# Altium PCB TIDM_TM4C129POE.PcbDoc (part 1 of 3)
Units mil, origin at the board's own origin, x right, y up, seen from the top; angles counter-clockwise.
Board outline 4950 x 3450 mil, 4 copper layers (Component Side, Ground Plane, Power Plane, Solder Side), stack 59.6 mil thick; 159 components, 154 nets, 570 pads, 297 vias.
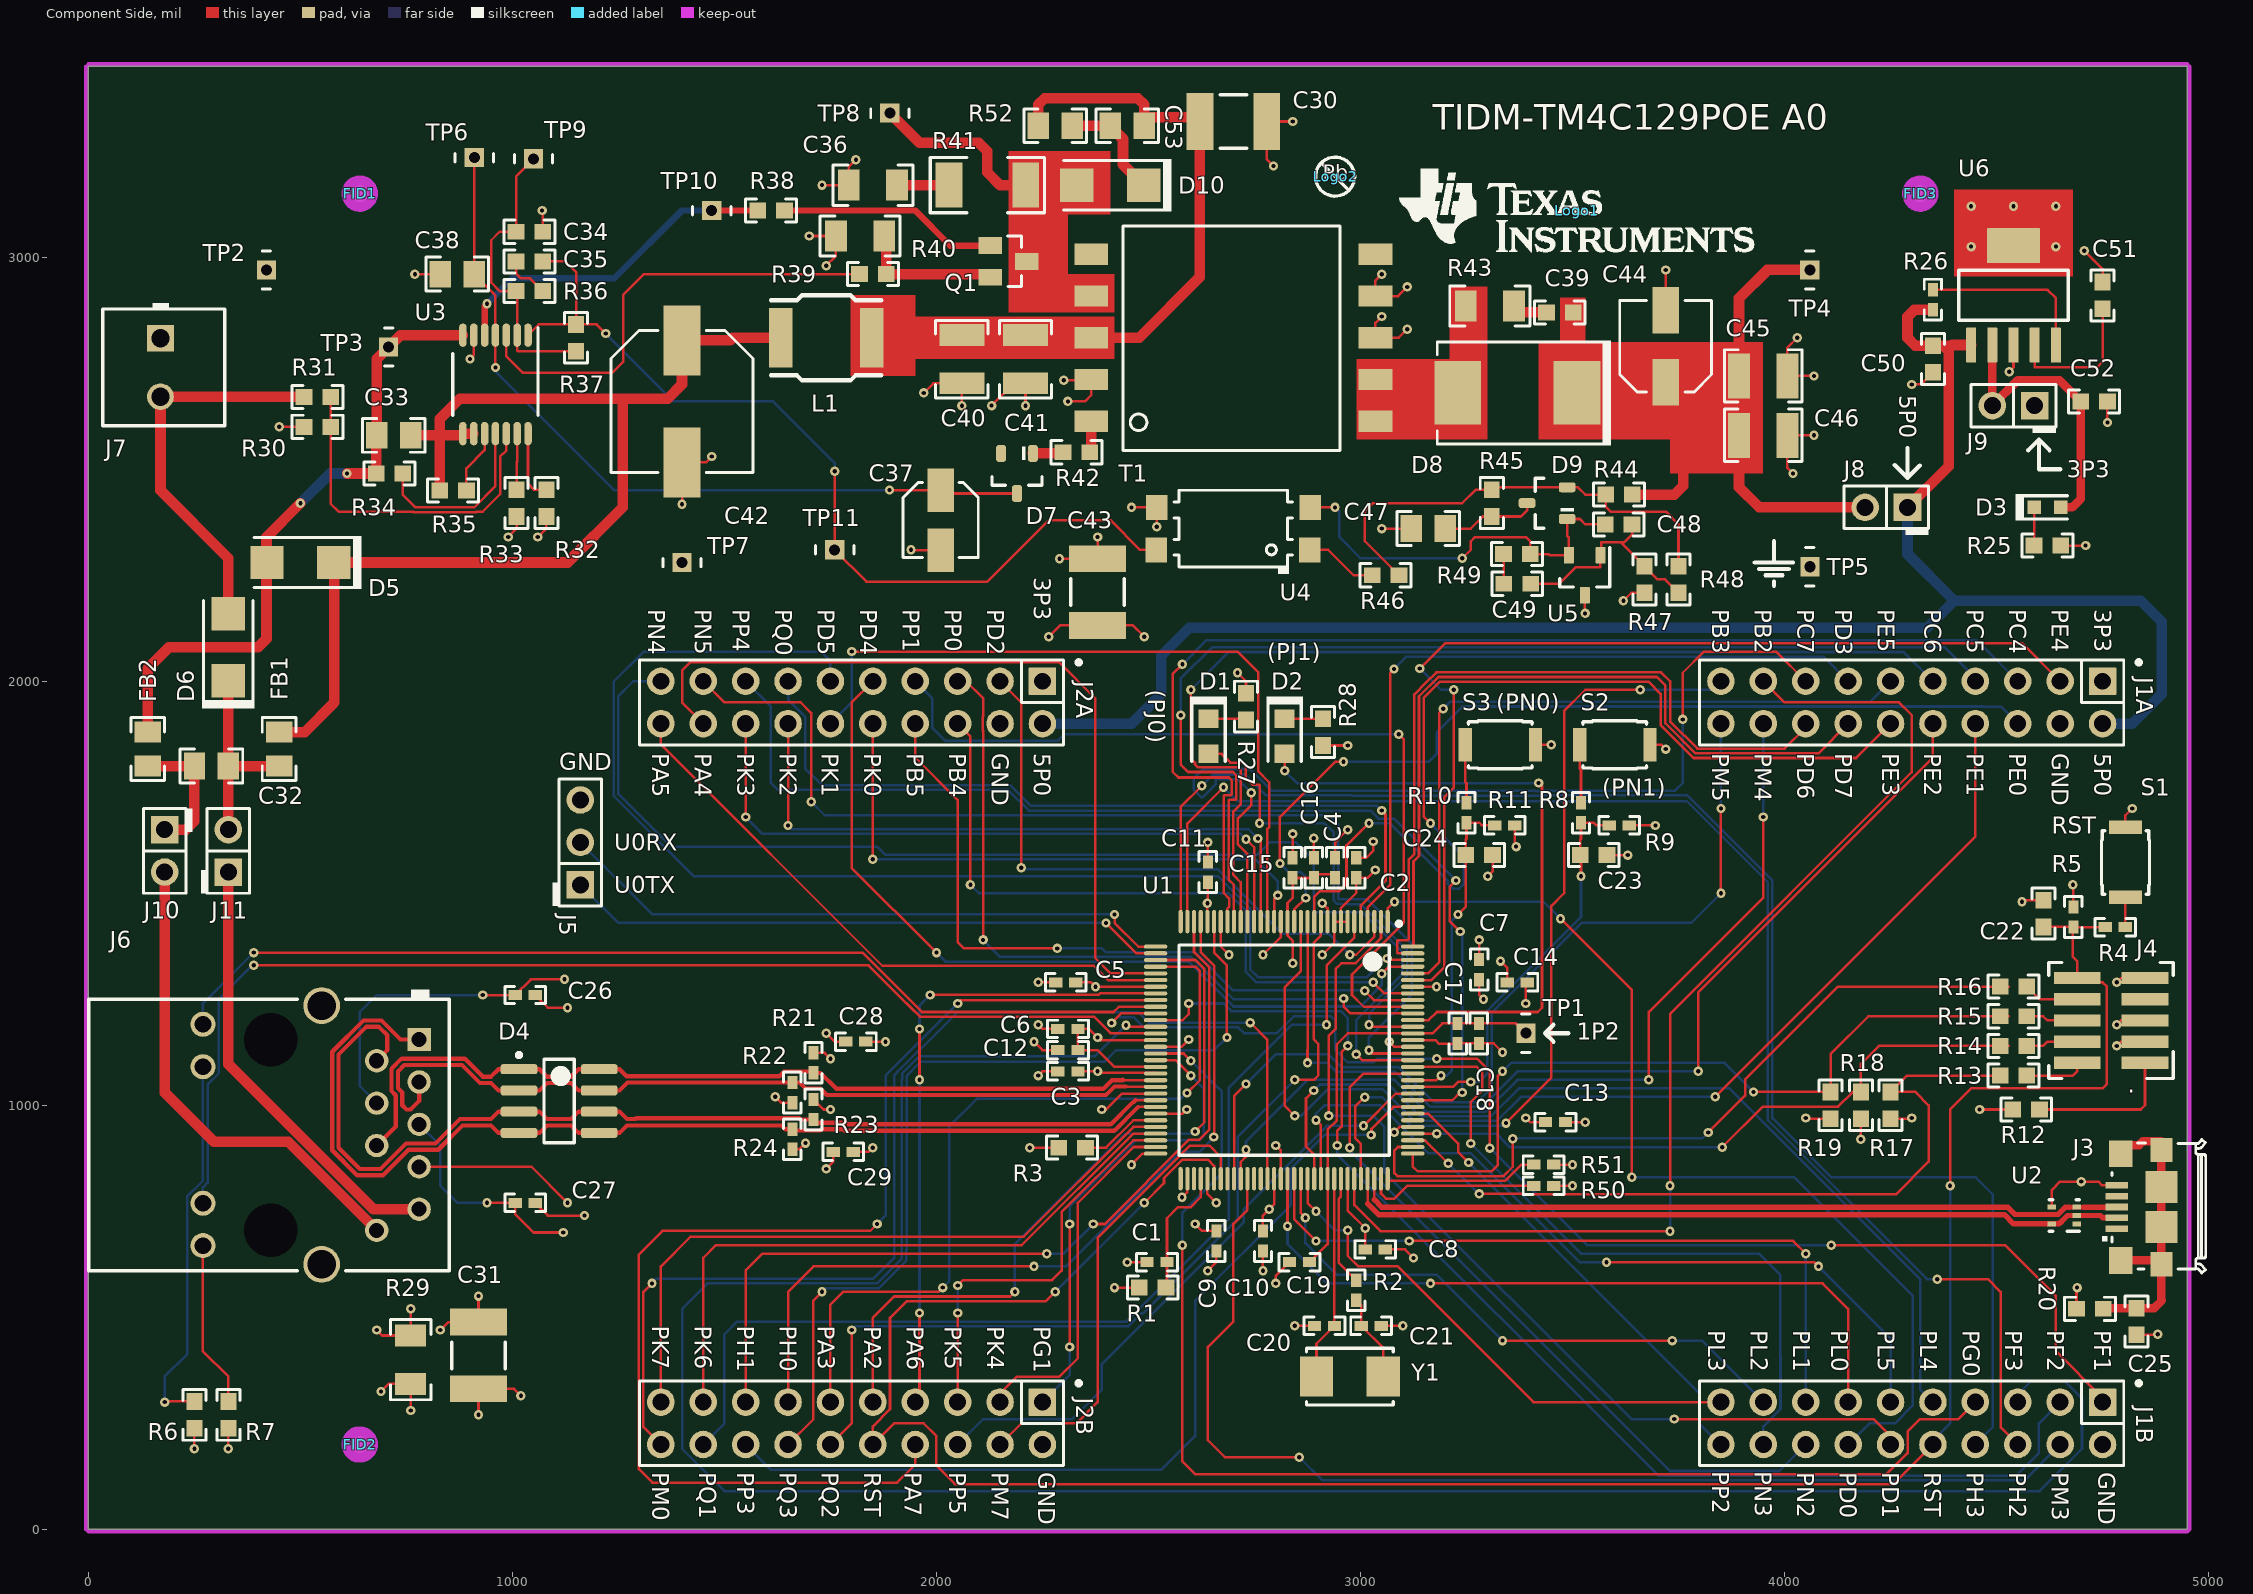
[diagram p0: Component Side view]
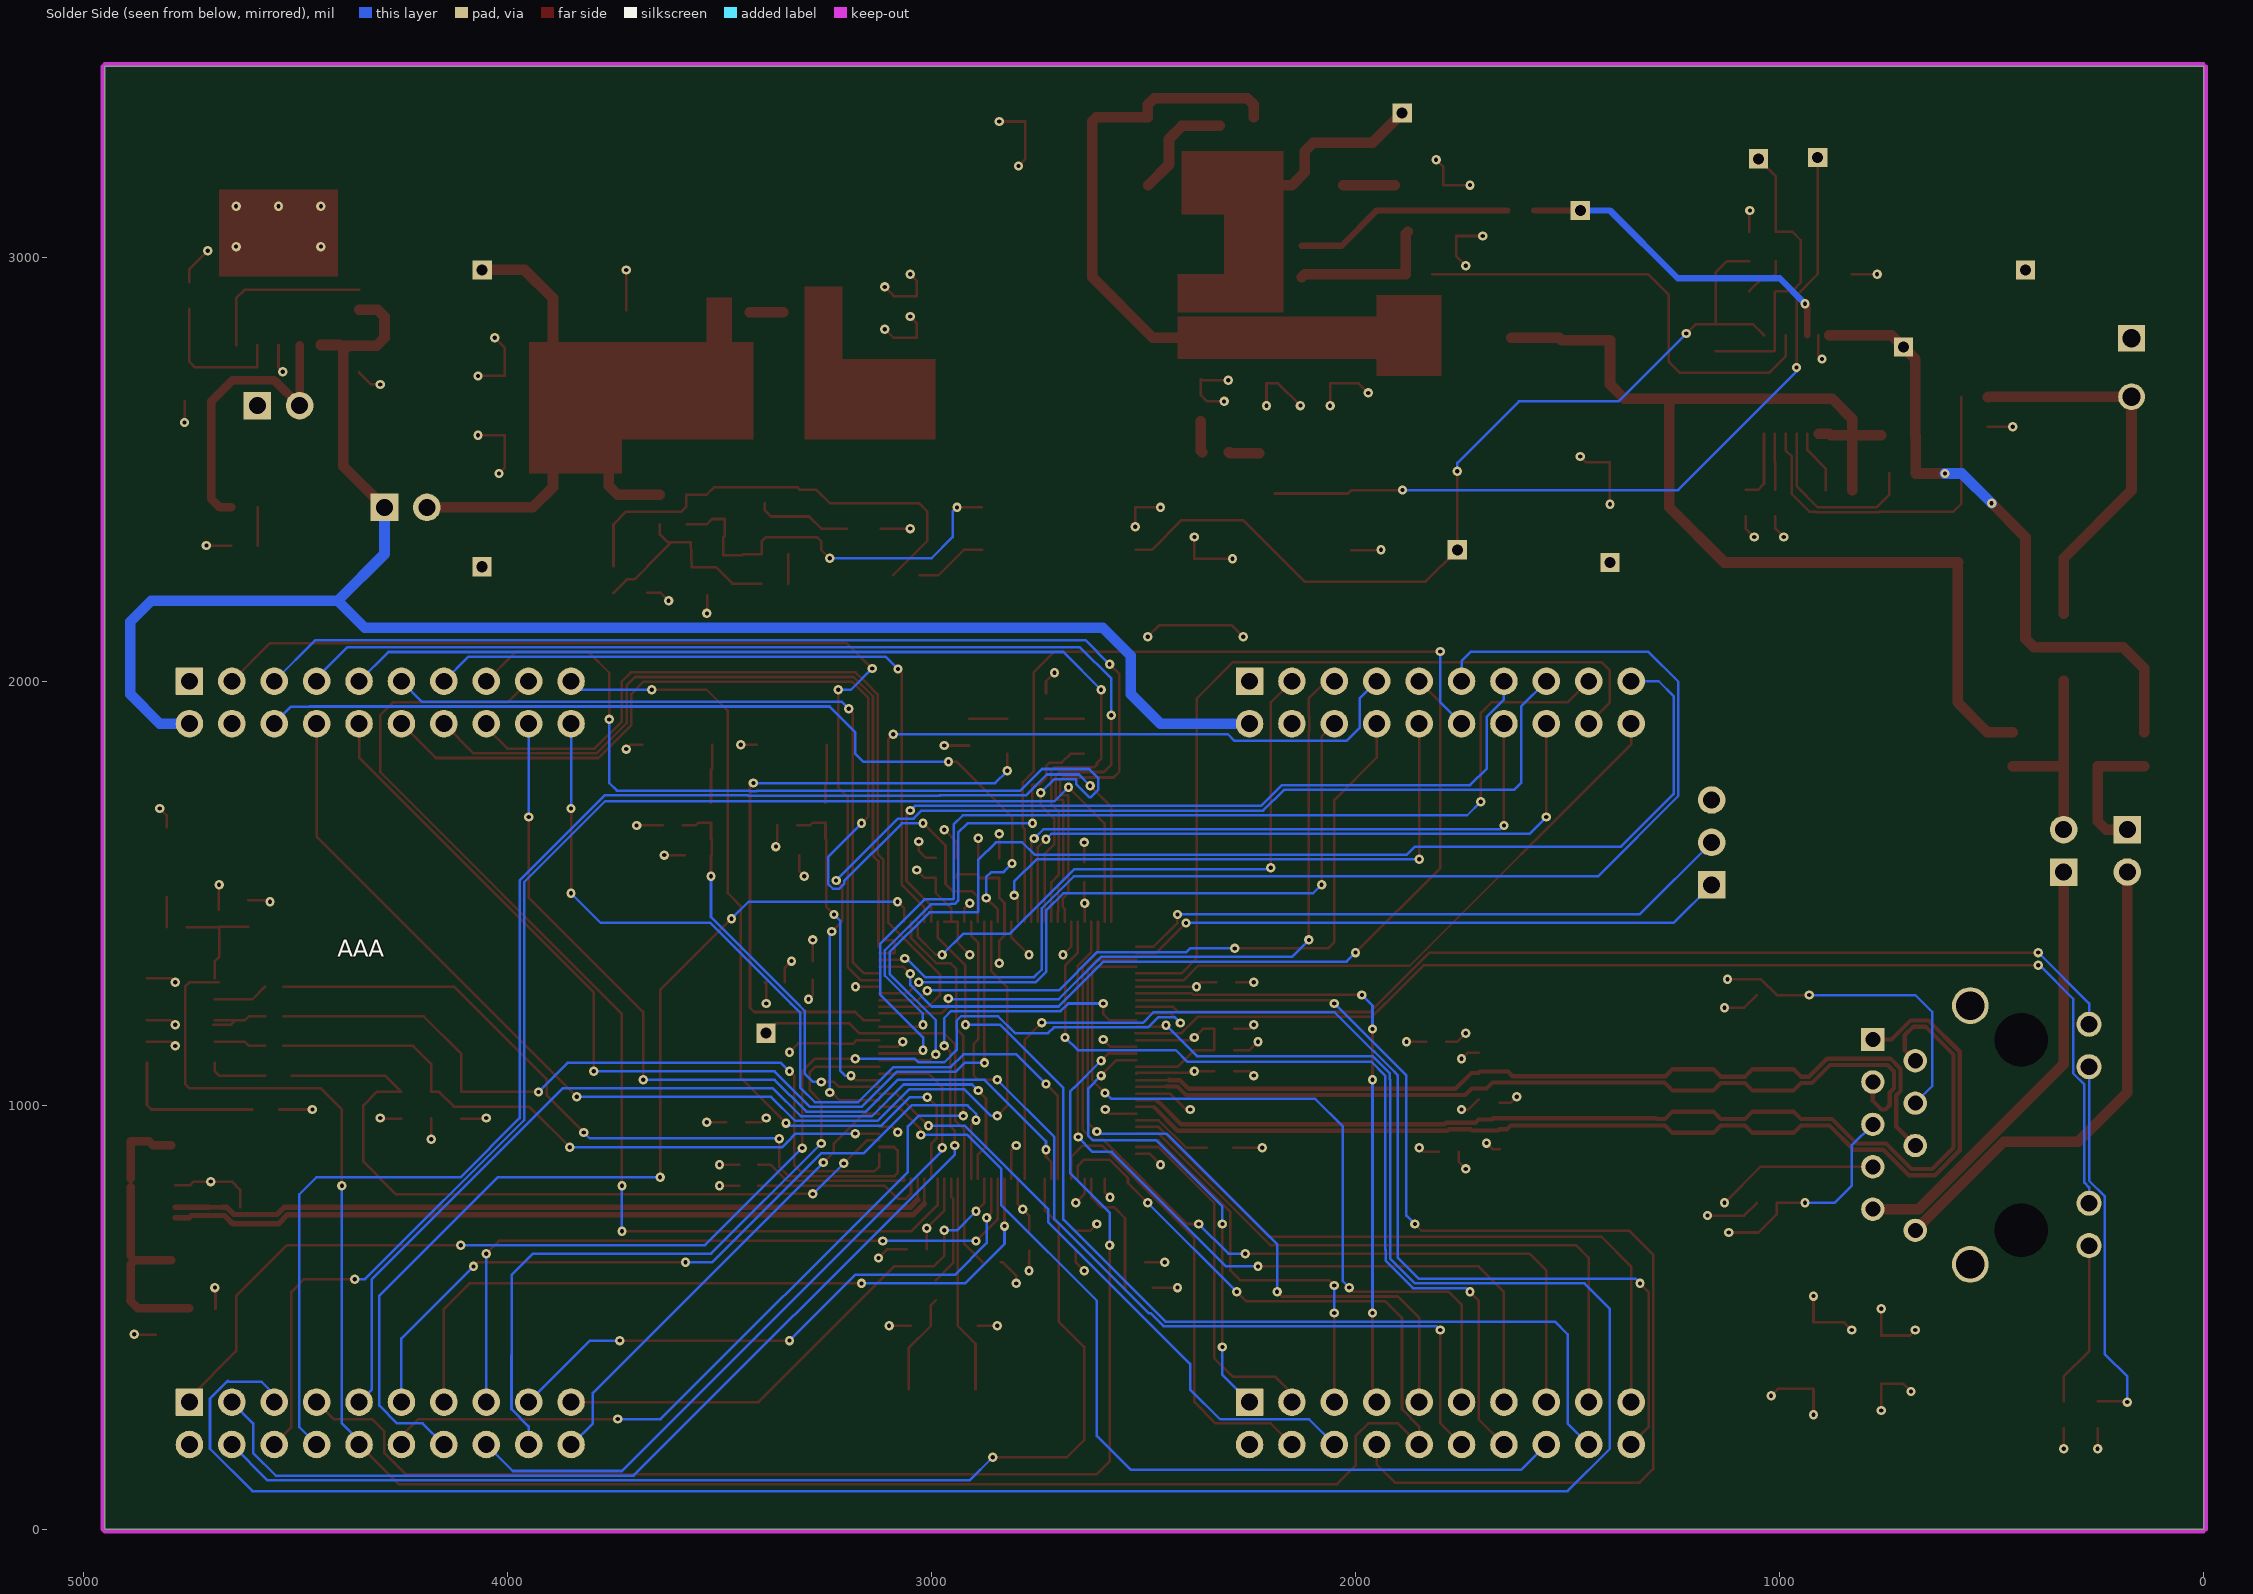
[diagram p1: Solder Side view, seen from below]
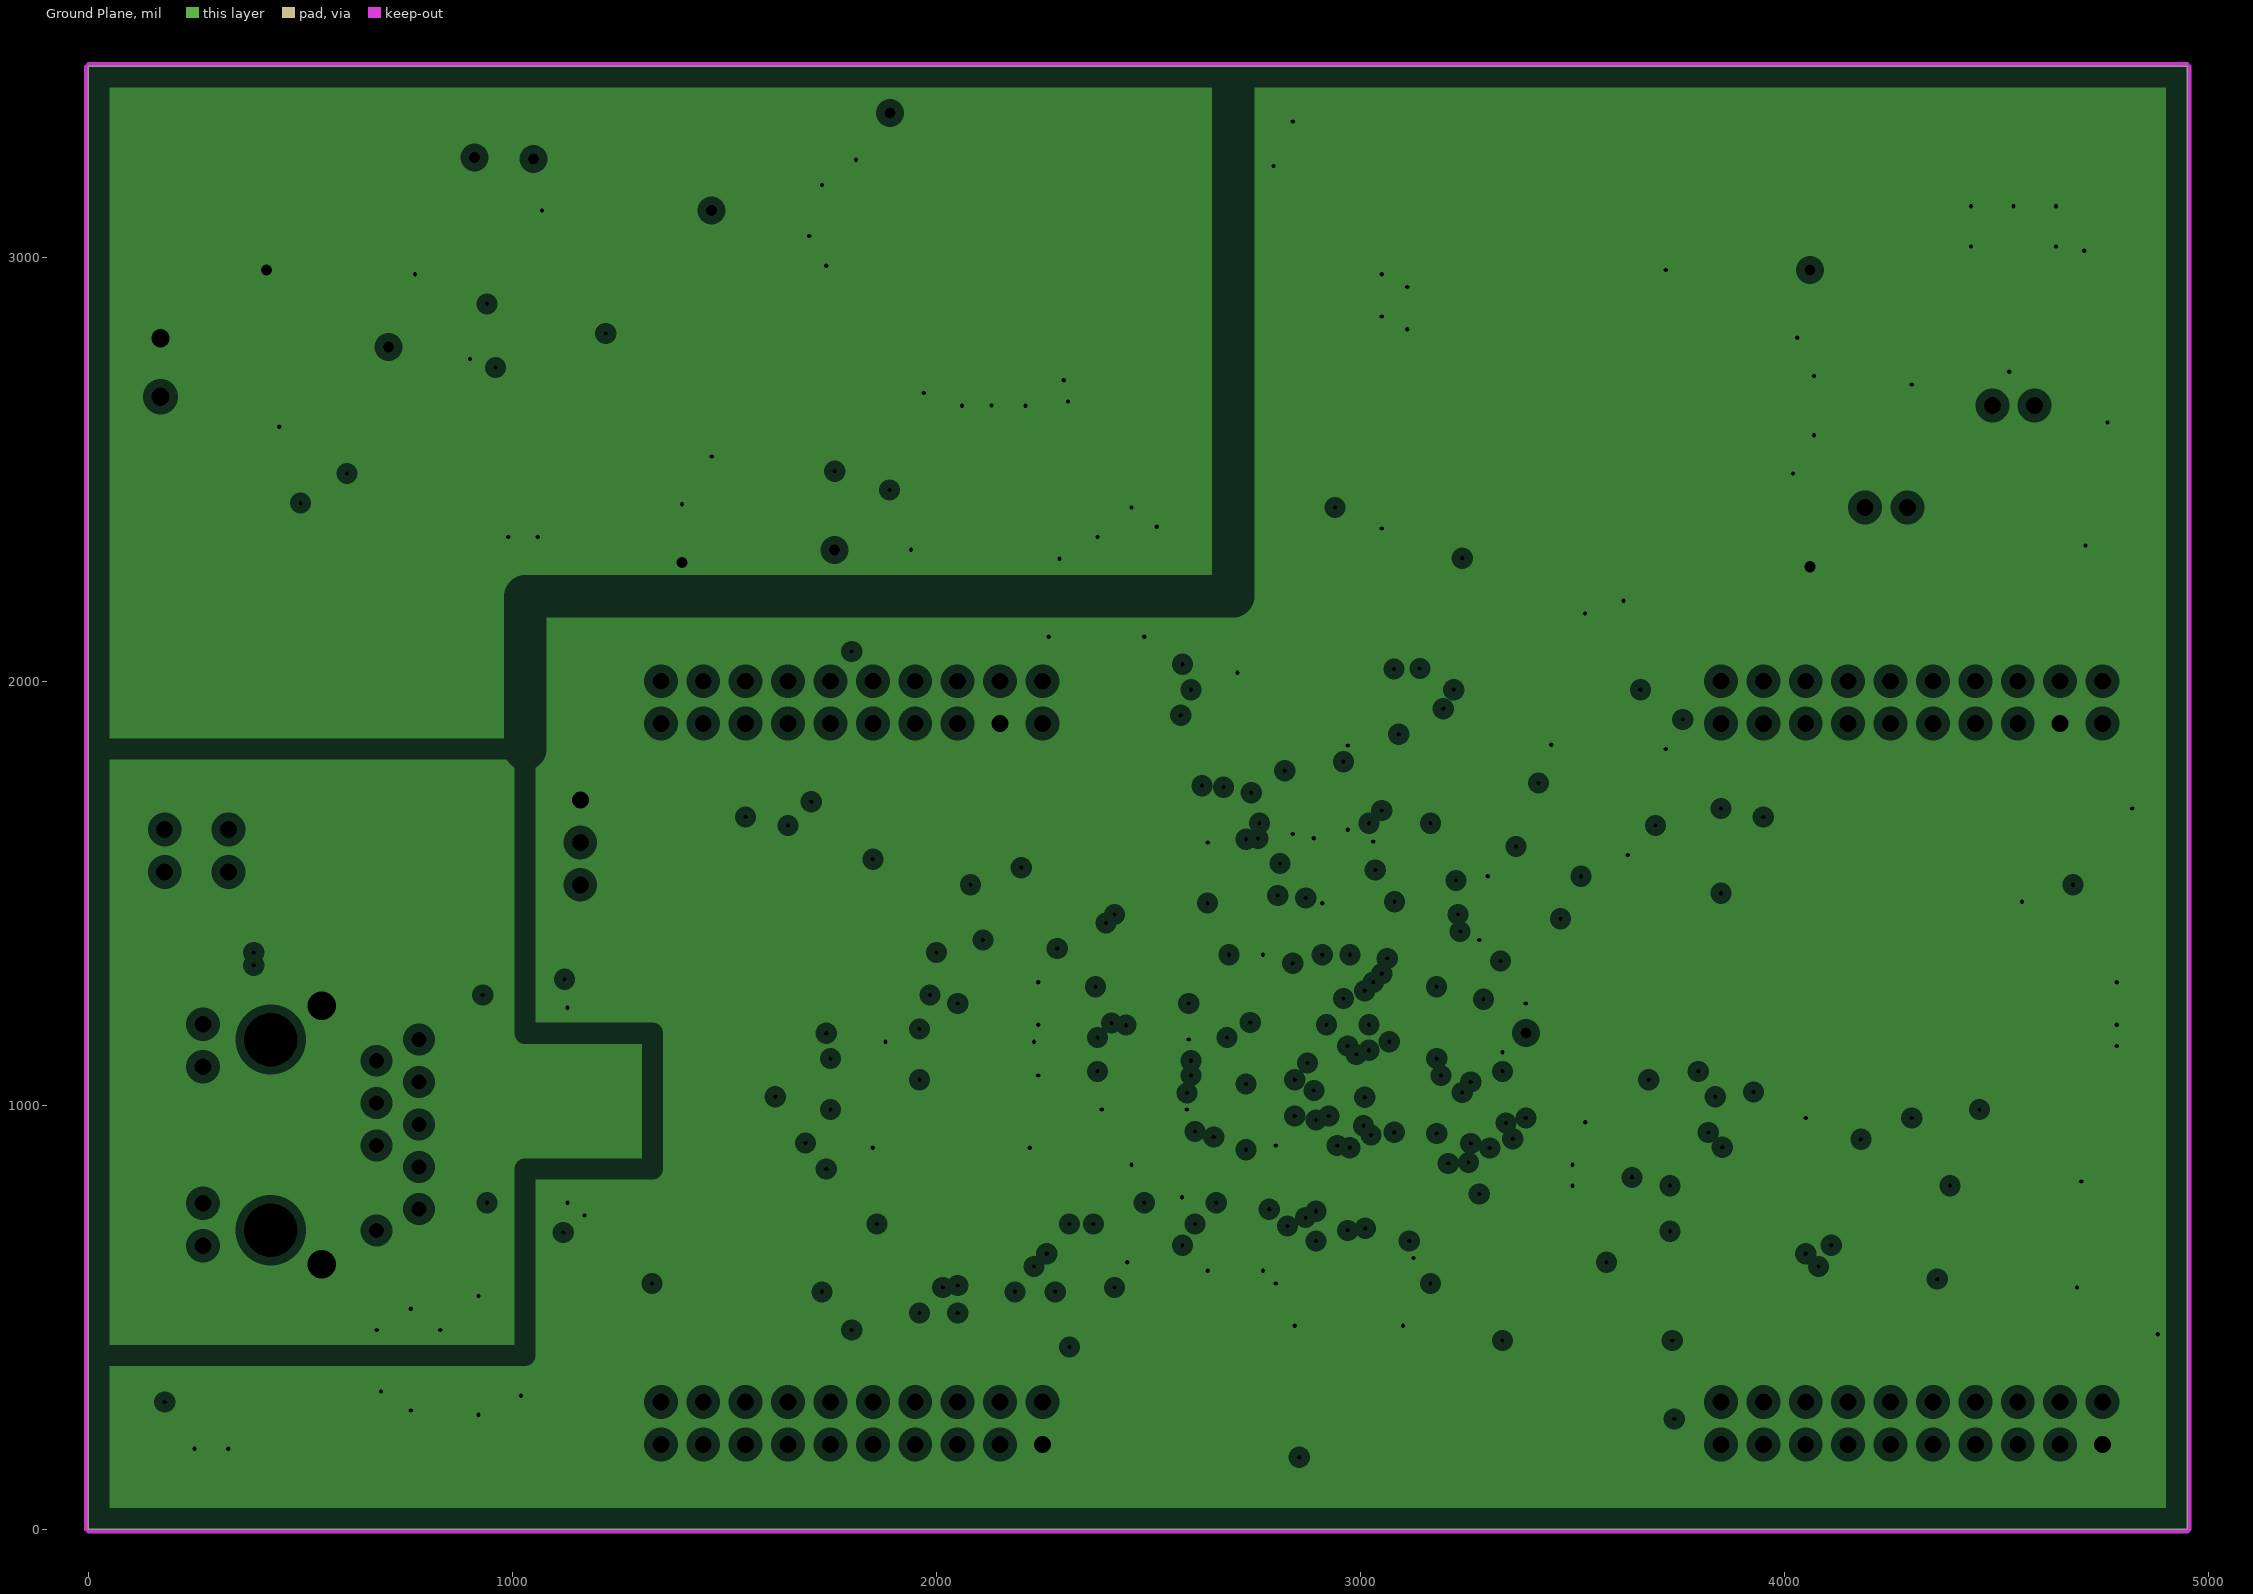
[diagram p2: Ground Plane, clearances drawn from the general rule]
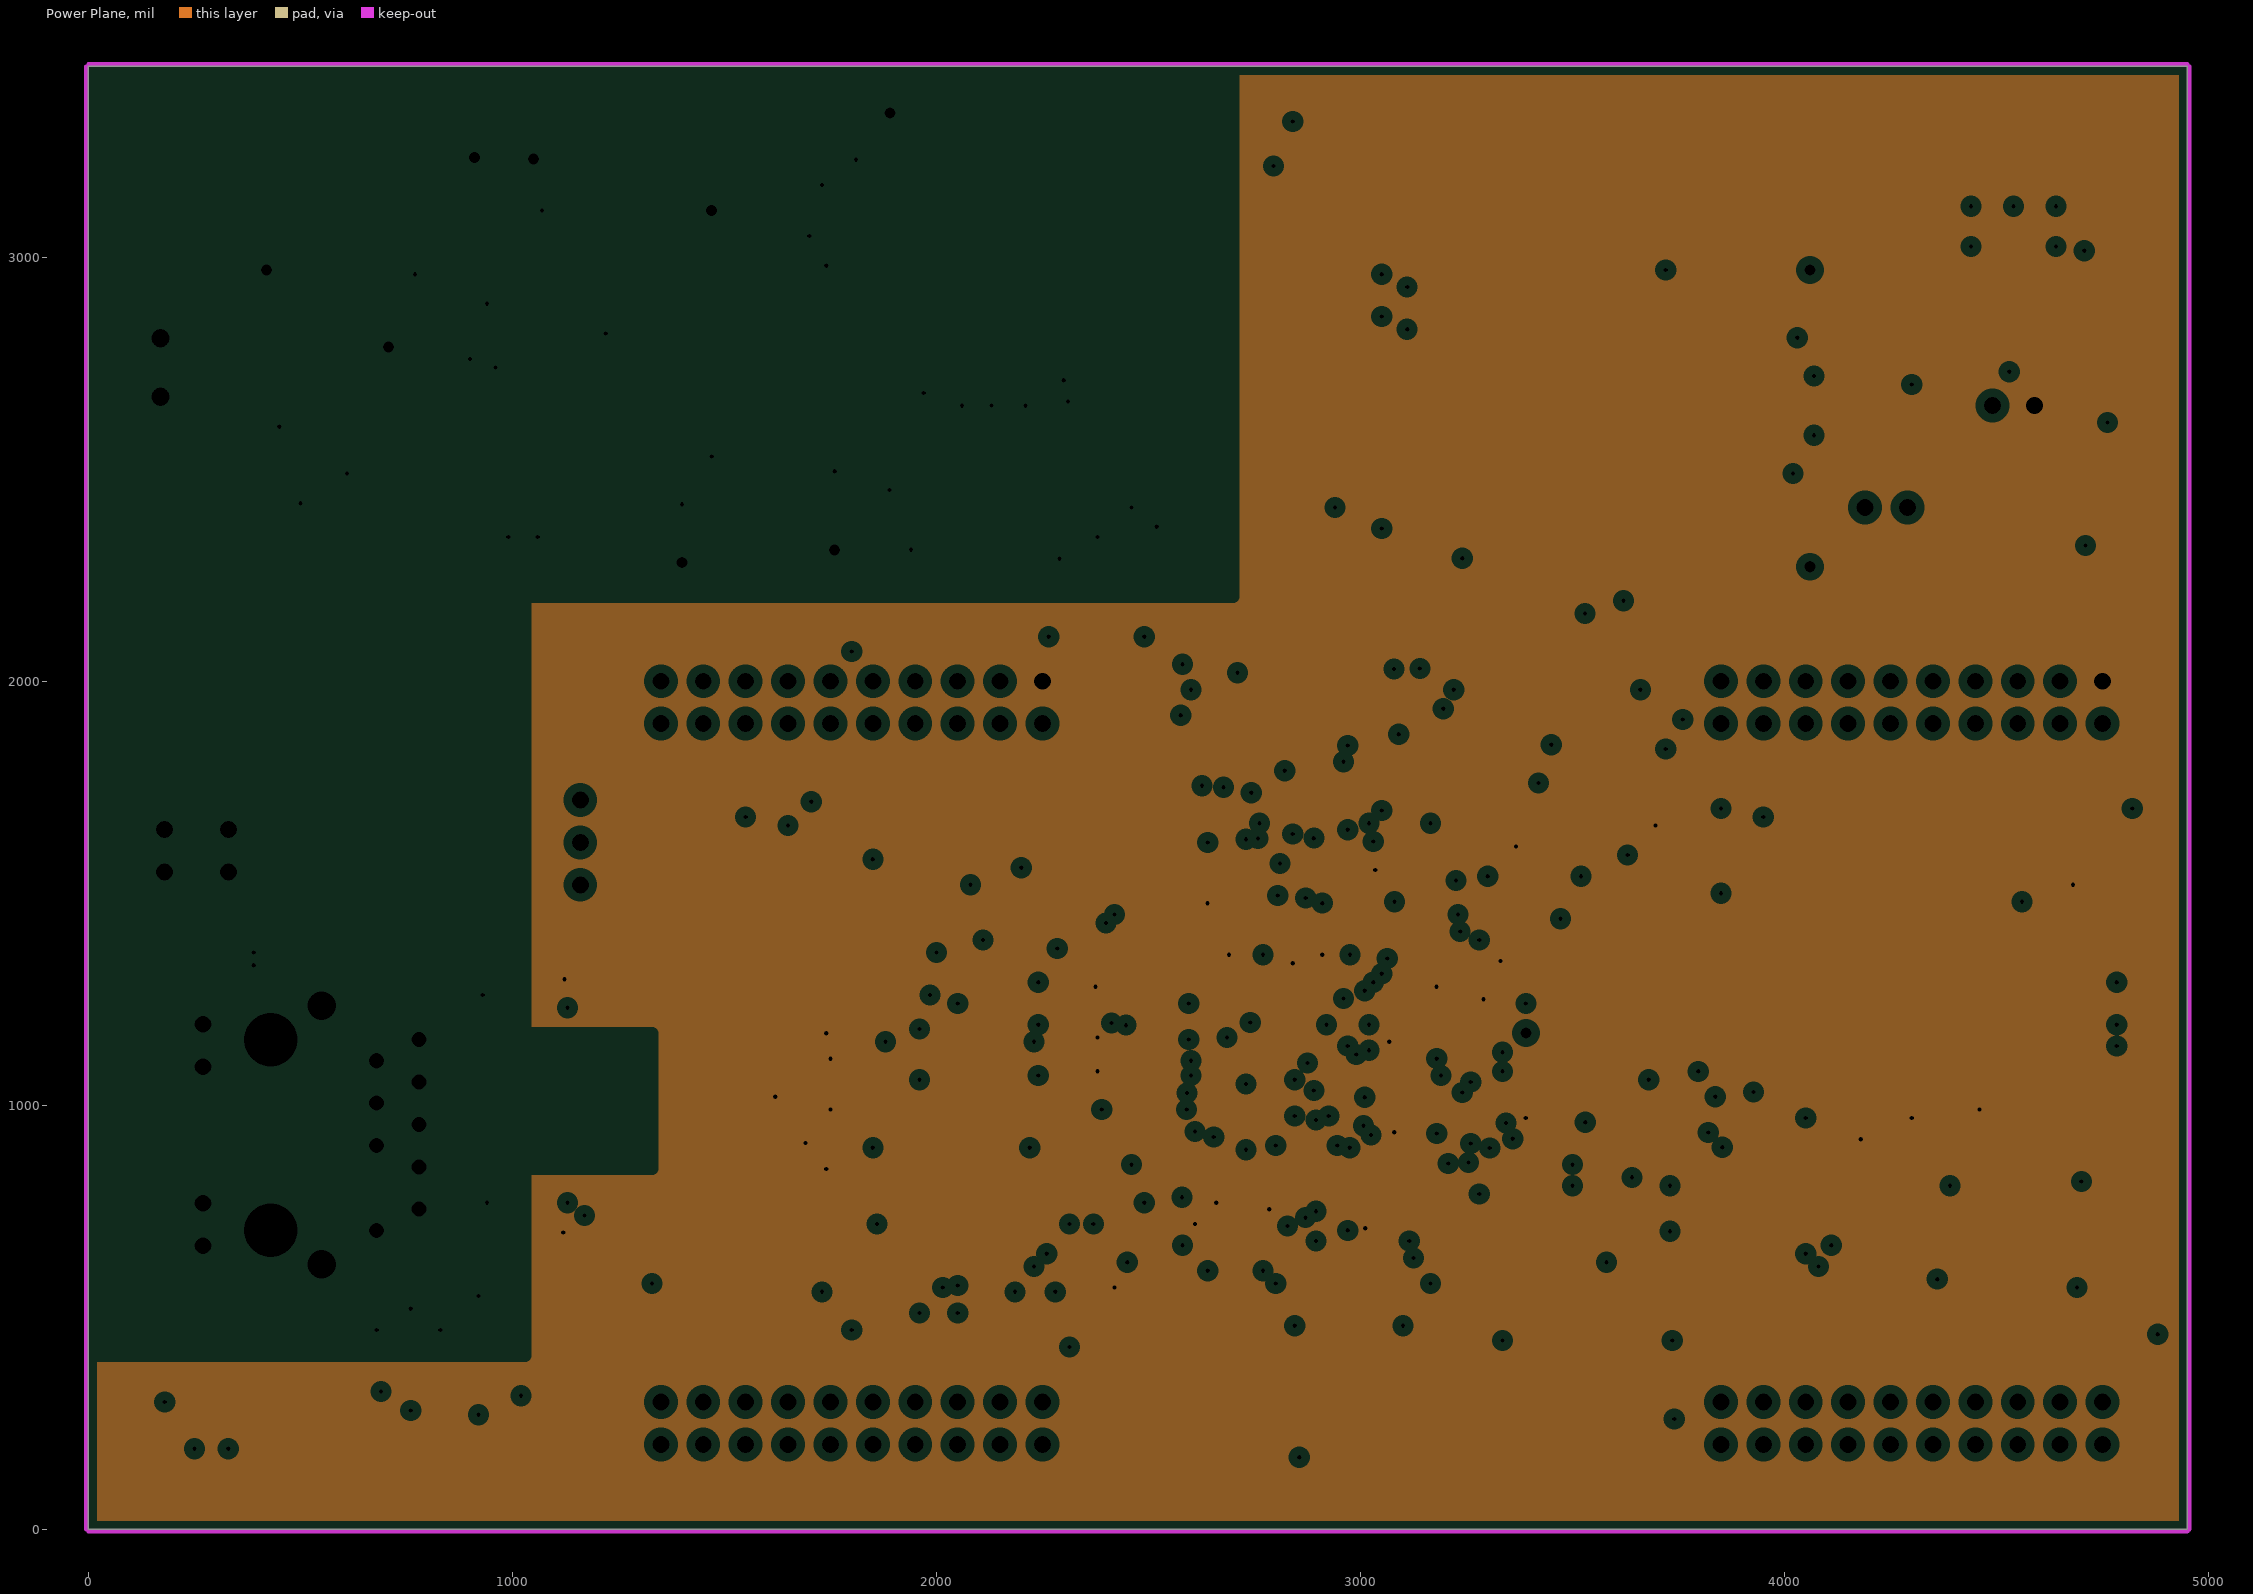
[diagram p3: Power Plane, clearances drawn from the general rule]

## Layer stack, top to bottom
Top Solder: solder mask 0.4, Solder Resist, Dk 3.5
Component Side: signal copper 1.4
Dielectric 1: core 13, FR-4, Dk 4.3
Ground Plane: plane copper 1.4, net (Multiple Nets)
Dielectric 3: prepreg 28, Dk 4.2
Power Plane: plane copper 1.4, net VCC_3P3
Dielectric 4: core 13, Dk 4.2
Solder Side: signal copper 1.4
Bottom Solder: solder mask 0.4, Solder Resist, Dk 3.5

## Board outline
0,0 4950,0 4950,3450 0,3450

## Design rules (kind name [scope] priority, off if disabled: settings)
AcuteAngle [All] p1: minimum=4.50000000000000E+0001 checktracksonly=FALSE
AssemblyTestPointUsage [All] p1: valid=2
Clearance ClearanceViaPWR2GND [(IsVia AND (InNet('GND') OR InNet('VCC_3P3'))) vs (IsVia AND (InNet('GND') OR InNet('VCC_3P3')))] p1: gap=40
Clearance Clearance_Keepouts [((IsTrack Or IsArc) And Not InPoly) And IsFree and IsKeepOut vs ((IsTrack Or IsArc) And Not InPoly) And IsFree and IsKeepOut] p2: gap=10
Clearance Clearance_BoardEdge_MountingHoles [OnCopper and InComponentClass('Mounting Holes') vs IsKeepOut] p3: gap=10
Clearance Clearance_BoardEdge_Poly [OnCopper and InPoly vs IsKeepOut] p4: gap=10
Clearance Clearance_BoardEdge [OnCopper and Not InComponentClass('Logo') and not InComponentClass('FiducialMark') and not InRegion(1000,500,4000,800) and Not IsKeepout vs IsKeepOut] p5: gap=10
Clearance Clearance_Poly [InPolygon] p6: gap=10
Clearance [All] p7: gap=5
ComponentClearance ComponentClearance_MountingHoles_FiducialMarks [InComponentClass('Mounting Holes') vs InComponentClass('FiducialMark')] p1: gap=50 collisioncheckmode=3 verticalgap=10 showdistances=FALSE
ComponentClearance ComponentClearance_Shunt [InComponentClass('Header') vs InComponentClass('Shunt')] p2: gap=0 collisioncheckmode=3 verticalgap=0 showdistances=FALSE
ComponentClearance ComponentClearance_Logo [InComponentClass('Logo')] p3: gap=50 collisioncheckmode=3 verticalgap=10 showdistances=FALSE
ComponentClearance ComponentClearance_ScrewToNut [(HasFootprint('NY PMS 440 0025 PH')) vs (HasFootprint('Keystone_1902C'))] p4: gap=5 collisioncheckmode=3 verticalgap=10 showdistances=FALSE
ComponentClearance ComponentClearance_MountingHoles [InComponentClass('Mounting Holes')] p5: gap=250 collisioncheckmode=3 verticalgap=100000 showdistances=FALSE
ComponentClearance ComponentClearance_SmallPassives [HasFootprint('0201*') or HasFootprint('0402*') or HasFootprint('0508') or HasFootprint('0603*') or HasFootprint('0612') or HasFootprint('0805*') or HasFootprint('0815*') or HasFootprint('0830*') or HasFootprint('1206*') or HasFootprint('1210*') or HasFootprint('1808*') or HasFootprint('1812*') or HasFootprint('1825*') or HasFootprint('2010*') or HasFootprint('2220*') or HasFootprint('2225*') or HasFootprint('2512*') or HasFootprint('2728*') or HasFootprint('3518*') vs HasFootprint('0201*') or HasFootprint('0402*') or HasFootprint('0508') or HasFootprint('0603*') or HasFootprint('0612') or HasFootprint('0805*') or HasFootprint('0815*') or HasFootprint('0830*') or HasFootprint('1206*') or HasFootprint('1210*') or HasFootprint('1808*') or HasFootprint('1812*') or HasFootprint('1825*') or HasFootprint('2010*') or HasFootprint('2220*') or HasFootprint('2225*') or HasFootprint('2512*') or HasFootprint('2728*') or HasFootprint('3518*')] p6: gap=20 collisioncheckmode=3 verticalgap=10 showdistances=FALSE
ComponentClearance ComponentClearance_THtoSMT [IsThruComponent vs IsSMTComponent] p7: gap=50 collisioncheckmode=3 verticalgap=30 showdistances=FALSE
ComponentClearance ComponentClearance_THtoTH [IsThruComponent vs IsThruComponent] p8: gap=40 collisioncheckmode=3 verticalgap=30 showdistances=FALSE
ComponentClearance [All] p9: gap=40 collisioncheckmode=3 verticalgap=10 showdistances=FALSE
DiffPairsRouting DiffPairsRoutingEth [(InNet('EPHYRX_N') OR InNet('EPHYRX_P') OR InNet('EPHYTX_N') OR InNet('EPHYTX_P'))] p1: maxlimit=50 minlimit=5 mostfreqgap=5 toplayer_minwidth=5 toplayer_maxwidth=11 toplayer_prefwidth=10 bottomlayer_minwidth=5 bottomlayer_maxwidth=11 bottomlayer_prefwidth=10 maxuncoupledlength=500
DiffPairsRouting DiffPairsRoutingUSB [InNet('USBD_N') OR InNet('USBD_P')] p2: maxlimit=300 minlimit=5 mostfreqgap=5 toplayer_minwidth=5 toplayer_maxwidth=14.73 toplayer_prefwidth=12.8 bottomlayer_minwidth=5 bottomlayer_maxwidth=14.73 bottomlayer_prefwidth=12.8 maxuncoupledlength=150
FabricationTestPointUsage TestPointUsage [All] p1: valid=2 allowmultiple=FALSE
FabricationTestpoint Testpoint [All] p1: side=3 testpointundercomponent=TRUE minsize=40 maxsize=100 preferedsize=60 minholesize=0 maxholesize=40 preferedholesize=32 testpointgrid=1 allowsidetop=TRUE allowsidebottom=TRUE usegrid=TRUE gridtolerance=0.01
FanoutControl Fanout_LCC [IsLCC] p1: bgadir=Out bgaviamode=Centered fanoutstyle=Auto fanoutdirection=Alternating viagrid=1 // Fanout_LCC (Default Rule)
FanoutControl Fanout_BGA [IsBGA] p2: bgadir=Out bgaviamode=Centered fanoutstyle=Auto fanoutdirection=Alternating viagrid=1 // Fanout_BGA (Default Rule)
FanoutControl Fanout_Default [All] p4: bgadir=Out bgaviamode=Centered fanoutstyle=Auto fanoutdirection=Alternating viagrid=1 // Fanout_Default (Default Rule)
FanoutControl Fanout_Small [(CompPinCount < 5)] p5: bgadir=Out bgaviamode=Centered fanoutstyle=Auto fanoutdirection=OutThenIn viagrid=1 // Fanout_Small (Default Rule)
HoleSize [All] p1: absolutevalues=TRUE maxlimit=251 minlimit=8 maxpercent=80.000 minpercent=20.000
MinimumAnnularRing MinimumAnnularRing_ThermalPadVias [IsVia and InAnyComponent] p1: minimumring=5.91
MinimumAnnularRing [All] p2: minimumring=6
MinimumSolderMaskSliver MinimumSolderMaskSliver_Logo [InComponentClass('Logo') vs InComponentClass('Logo')] p1: minsoldermaskwidth=0.7
MinimumSolderMaskSliver [All] p2: minsoldermaskwidth=1.96
PlaneClearance [All] p1: clearance=20
PlaneConnect [All] p1: planeconnectstyle=Relief reliefexpansion=13 reliefentries=4 reliefconductorwidth=10 reliefairgap=10
PolygonConnect [All] p1: connectstyle=Relief reliefconductorwidth=10 reliefentries=4 polygonreliefangle="90 Angle" airgapwidth=10
RoomDefinition RoomTM4C129 [HasFootprint('PDT0128A_N')] p1: confinementstyle=ConfineIn formatcopy=TRUE lockcomponents=FALSE outline 2438.46,770 2438.46,1511.54 3201.54,1511.54 3201.54,770
RoomDefinition RoomUSBESD [HasFootprint('DRY0006A')] p2: confinementstyle=ConfineIn formatcopy=TRUE lockcomponents=FALSE outline 4610,705.31 4610,800.31 4710,800.31 4710,705.31
RoutingLayers DiffPairRoutingLayer [(InDifferentialPairClass('All Differential Pairs'))] p1: top layer_v5=TRUE bottom layer_v5=FALSE
RoutingLayers [All] p2: top layer_v5=TRUE bottom layer_v5=TRUE
RoutingVias ThermalPadVias [IsVia and InAnyComponent] p1: holewidth=7.87 width=19.68 viastyle="Through Hole" minholewidth=7.87 minwidth=19.68 maxholewidth=12.99 maxwidth=23.62
RoutingVias [All] p2: holewidth=10 width=22 viastyle="Through Hole" minholewidth=10 minwidth=22 maxholewidth=15 maxwidth=27
SMDNeckDown DiffSMDNeckDown [(InDifferentialPairClass('All Differential Pairs'))] p1: percent=90.000
SMDNeckDown [All] p2: percent=80.000
SilkToBoardRegionClearance [Not ((IsComment or IsDesignator) And (Hide <> 'False')) and not InRegion(1000,500,4000,800)] p1:
SilkToSilkClearance SilkToSilkClearance_Pb-FreeLogo [(HasFootprint('Pb-Free_Overlay_Medium') OR HasFootprint('Pb-Free_Overlay_Small')) vs (HasFootprint('Pb-Free_Overlay_Medium') OR HasFootprint('Pb-Free_Overlay_Small'))] p1: silktosilkclearance=0
SilkToSilkClearance [All] p2: silktosilkclearance=4
SilkToSolderMaskClearance SilkToComonentPadClearance [IsPad and InAnycomponent] p1: minsilkscreentomaskgap=5 clearancetoexposedcopper=TRUE
SilkToSolderMaskClearance "Silk to Solder Mask Opening" [All] p2: minsilkscreentomaskgap=4 clearancetoexposedcopper=FALSE
SolderMaskExpansion SolderMaskExpansion_1 [IsVia] p1: expansion=-20
SolderMaskExpansion [All] p2: expansion=1.97
UnpouredPolygon [All] p1: allowunpoured=FALSE
Width RoomWidthRule [TouchesRoom('RoomTM4C129') OR TouchesRoom('RoomUSBESD')] p1: maxlimit=8 minlimit=6 preferedwidth=6
Width DiffPairWidth [(InDifferentialPairClass('All Differential Pairs'))] p2: maxlimit=23.16 minlimit=2.99 preferedwidth=4.64 toplayer_maxwidth=22.86 toplayer_prefwidth=4.48 bottomlayer_minwidth=3.11 impedancedriven=TRUE minimp=50.000000 maximp=110.000000 favimp=100.000000
Width TRCWidth [(InNet('TRC_*'))] p3: maxlimit=20 minlimit=15 preferedwidth=15
Width 3P3Width [InNet('NetC52_1')] p4: maxlimit=30 minlimit=20 preferedwidth=20
Width PoENETRule [(InNet('POE_*') OR InNet('VCC_5P0'))] p5: maxlimit=30 minlimit=25 preferedwidth=25
Width ChassisWidth [(InNet('NetC30_1') OR InNet('NetC25_1'))] p6: maxlimit=30 minlimit=20 preferedwidth=20
Width [All] p7: maxlimit=10 minlimit=6 preferedwidth=6
12 further rules are at their usual default settings.

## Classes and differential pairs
component class "Room Definition 2": U1
component class "Room Definition 1": U2
component class FiducialMark: FID1 FID2 FID3
component class Logo: Logo1
component class Header: J1A J1B J2A J2B J4 J5 J8 J9 J10 J11
component class TIDM_TM4CPOEGATEWAY_Connector: C23 C24 C25 D1 D2 FID1 FID2 FID3 J3 J4 J5 Logo1 Logo2 R8 R9 R10 R11 R12 R13 R14 R15 R16 R17 R18 R19 R20 R27 R28 S2 S3 U2
component class TIDM_TM4CPOEGATEWAY_Ethernet: C26 C27 C28 C29 C31 D4 J6 J10 J11 R6 R7 R21 R22 R23 R24 R29
component class TIDM_TM4CPOEGATEWAY_Micro: C1 C2 C3 C4 C5 C6 C7 C8 C9 C10 C11 C12 C13 C14 C15 C16 C17 C18 C19 C20 C21 C22 J1A J1B J2A J2B R1 R2 R3 R4 R5 R50 R51 S1 TP1 U1 Y1
component class TIDM_TM4CPOEGATEWAY_PowerStage: C30 C32 C33 C34 C35 C36 C37 C38 C39 C40 C41 C42 C43 C44 C45 C46 C47 C48 C49 C50 C51 C52 C53 D3 D5 D6 D7 D8 D9 D10 FB1 FB2 J7 J8 J9 L1 Q1 R25 R26 R30 R31 R32 R33 R34 R35 R36 R37 R38 R39 R40 R41 R42 R43 R44 R45 R46 R47 R48 R49 R52 T1 TP2 TP3 TP4 TP5 TP6 TP7 TP8 TP9 TP10 TP11 U3 U4 U5 U6
differential pair EPHYRX: +EPHYTX_P -EPHYTX_N
differential pair EPHYTX: +EPHYRX_P -EPHYRX_N
differential pair USBD: +USBD_P -USBD_N

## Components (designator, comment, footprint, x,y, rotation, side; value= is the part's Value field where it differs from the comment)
C1 "GRM155R71C104KA88D" 0402 2520.02,630 r180 top
C2 "C1005X5R1C105K050BC" 0402 2990,1560 r90 top
C3 "GRM155R71C104KA88D" 0402 2310,1080 r180 top
C4 "GRM155R71C104KA88D" 0402 2940,1560 r90 top
C5 "GRM155R71C104KA88D" 0402 2305,1290 r180 top
C6 "GRM155R71C104KA88D" 0402 2310,1180 r180 top
C7 "GRM155R71C104KA88D" 0402 3280,1320 r90 top
C8 "GRM155R71C104KA88D" 0402 3035,660 r0 top
C9 "GRM155R71C104KA88D" 0402 2660,680 r270 top
C10 "GRM155R71C104KA88D" 0402 2770,680 r270 top
C11 "GRM155R71C104KA88D" 0402 2640,1550 r90 top
C12 "GRM155R71C104KA88D" 0402 2310,1130 r180 top
C13 "GRM155R71C104KA88D" 0402 3460,960 r0 top
C14 "GRM155R71C104KA88D" 0402 3370,1290 r0 top
C15 "GRM155R71C103KA01D" 0402 2840,1560 r90 top
C16 "GRM155R71C103KA01D" 0402 2890,1560 r90 top
C17 "GRM155R61C225KE11D" 0402 3228.97,1169.37 r270 top
C18 "C1005X5R1C105K050BC" 0402 3279,1169.4 r270 top
C19 "GRM155R71C104KA88D" 0402 2856.24,630 r180 top
C20 "C1005C0G1H220J050BA" 0402 2915,480 r180 top
C21 "C1005C0G1H220J050BA" 0402 3025,480 r0 top
C22 "C0603C104J3RAC" 0603 4611,1452 r90 top
C23 "C0603C104J3RAC" 0603 3550,1590 r0 top
C24 "C0603C104J3RAC" 0603 3280,1590 r0 top
C25 "C0603X332K5RACTU" 0603 4830,490 r270 top
C26 "GCM155R71C104KA55D" 0402 1030,1260 r0 top
C27 "GCM155R71C104KA55D" 0402 1030,770 r0 top
C28 "GCM155R71C104KA55D" 0402 1810,1150 r0 top
C29 "GCM155R71C104KA55D" 0402 1780,890 r0 top
C30 "C4532X7R3D222K" 1812 2700,3320 r180 top
C31 "1812GC472KA1" 1812 920,410 r270 top
C32 "08051C102KAT2A" 0805_HV 290,1800 r180 top
C33 "C0805C104K1RACTU" 0805_HV 720,2580 r180 top
C34 "C1608X7R1H104K" 0603 1040,3060 r0 top
C35 "C1608X7R1H223K" 0603 1040,2990 r0 top
C36 "GRM31A5C2J331JW01D" 1206 1850,3170 r180 top
C37 "EMVE160ADA100MD55G" CAPSMT_62_D55 2010,2380 r270 top
C38 "08053C224KAT2A" 0805_HV 870,2960 r180 top
C39 "C0603C681K5RACTU" 0603 3470,2870 r180 top
C40 "C3225X7R2A105K200AA" 1210 2060,2759.69 r270 top
C41 "C3225X7R2A105K200AA" 1210 2210,2759.69 r270 top
C42 "EMVH630ADA220MHA0G" CAPSMT_62_HA0 1400,2660 r270 top
C43 "C4532X7R3D222K" 1812 2380,2210.32 r90 top
C44 "EEE-FK0J470R" SM_RADIAL_C 3719.68,2790 r90 top
C45 "GRM32ER61A476KE20L" 1210 3949.68,2720 r0 top
C46 "GRM32ER61A476KE20L" 1210 3949.68,2580 r0 top
C47 "C2012X7R1C105K" 0805_HV 3159.68,2360 r180 top
C48 "06035A101JAT2A" 0603 3608.93,2370 r180 top
C49 "GRM188R71H822KA01D" 0603 3369.68,2230 r180 top
C50 "EMK107B7104KA-T" 0603 4350,2760 r270 top
C51 "EMK107B7104KA-T" 0603 4750,2910 r90 top
C52 "GRM188R61C225KE15D" 0603 4730,2660 r0 top
C53 "GRM21BR72A103KA01L" 0805_HV 2450,3310 r180 top
D1 "150080SS75000" WL-SMCW_RED_0805 2641.3,1870 r270 top
D2 "150080SS75000" WL-SMCW_RED_0805 2821.3,1870 r270 top
D3 "150060GS75000" WL-SMCW_GREEN 4620,2410 r0 top
D4 "SLVU2.8-4.TBT" SO-8 1110,1010 r0 top
D5 "SMAJ58A" SMA 500,2280 r180 top
D6 "MURA120T3G" SMA 330,2080 r90 top
D7 "BAS16-7-F" SOT-23 2190,2490 r270 top
D8 "MBRS540T3G" SMC 3370,2680 r180 top
D9 "BAV99,215" SOT-23 3440,2420 r180 top
D10 "MURA120T3G" SMA 2410,3170 r180 top
FB1 "MMZ2012R300A" 0805_HV 450,1840 r90 top
FB2 "MMZ2012R300A" 0805_HV 140,1840 r90 top
FID1 "Fiducial" Fiducial10-20 640,3150 r0 top
FID2 "Fiducial" Fiducial10-20 640,200 r0 top
FID3 "Fiducial" Fiducial10-20 4320,3150 r0 top
J1A "TSW-110-07-G-D" TSW-110-07-G-D 4300,1950 r180 top
J1B "TSW-110-07-G-D" TSW-110-07-G-D 4300,250 r180 top
J2A "TSW-110-07-G-D" TSW-110-07-G-D 1800,1950 r180 top
J2B "TSW-110-07-G-D" TSW-110-07-G-D 1800,250 r180 top
J3 "1981568-1" TE_1981568-1 4950,760 r90 top
J4 "FTSH-105-01-F-DV" Samtec_FTSH-105-01-x-DV 4770,1200 r180 top
J5 "TSW-103-07-G-S" TSW-103-07-G-S 1160,1620 r90 top
J6 "ARJP11A-MASA-B-A-EMU2" Abracon_ARJP11A 430,930 r270 top
J7 "39357-0002" Molex_39357-0002 170,2740 r270 top
J8 "TSW-102-07-G-S" TSW-102-07-G-S 4240,2410 r180 top
J9 "TSW-102-07-G-S" TSW-102-07-G-S 4540,2650 r180 top
J10 "TSW-102-07-G-S" TSW-102-07-G-S 180,1600 r270 top
J11 "TSW-102-07-G-S" TSW-102-07-G-S 330,1600 r90 top
L1 "DO1608C-472MLB" DO1608C 1740,2810 r0 top
Logo1 "Texas Instruments" TI_Stacked_Overlay_Small 3510,3110 r0 top
Logo2 "Pb-Free Symbol" Pb-Free_Overlay_Small 2940,3190 r0 top
Q1 "FDN86246" SSOT-3 2170,2990 r270 top
R1 "CRCW060351R0JNEA" 0603 2510,570 r0 top
R2 "ERJ-2GE0R00X" 0402 2990,563.62 r270 top
R3 "CRCW06034K87FKEA" 0603 2320,900 r0 top
R4 "CRCW0402100RJNED" 0402 4780,1420 r0 top
R5 "CRCW040210K0JNED" 0402 4681,1444 r90 top
R6 "RC0603JR-07330RL" 0603 250,270 r270 top
R7 "RC0603JR-07330RL" 0603 330,270 r270 top
R8 "CRCW0402100RJNED" 0402 3520,1690 r90 top
R9 "CRCW040210K0JNED" 0402 3610,1660 r0 top
R10 "CRCW0402100RJNED" 0402 3250,1690 r90 top
R11 "CRCW040210K0JNED" 0402 3340,1660 r0 top
R12 "CRCW0603100RJNEA" 0603 4570,990 r0 top
R13 "CRCW060333R0JNEA" 0603 4540,1070 r180 top
R14 "CRCW060333R0JNEA" 0603 4540,1140 r180 top
R15 "CRCW060333R0JNEA" 0603 4540,1210 r180 top
R16 "CRCW060333R0JNEA" 0603 4540,1280 r180 top
R17 "CRCW060310K0JNEA" 0603 4250,1000 r270 top
R18 "CRCW060310K0JNEA" 0603 4180,1000 r270 top
R19 "CRCW060310K0JNEA" 0603 4108.7,1000 r90 top
R20 "CRCW06031M00JNEA" 0603 4720,520 r0 top
R21 "CRCW040249R9FKED" 0402 1710,1100 r90 top
R22 "CRCW040249R9FKED" 0402 1660,1030 r270 top
R23 "CRCW040249R9FKED" 0402 1710,990 r90 top
R24 "CRCW040249R9FKED" 0402 1660,920 r270 top
R25 "RC0603JR-07330RL" 0603 4620,2320 r0 top
R26 "ERJ-2RKF1003X" 0402 4350,2900 r90 top
R27 "RC0603JR-07330RL" 0603 2730,1940 r90 top
R28 "RC0603JR-07330RL" 0603 2911.3,1880 r270 top
R29 "CRCW12061M00JNEA" 1206 760,400 r90 top
R30 "CRCW060339K2FKEA" 0603 540,2600 r0 top
R31 "CRCW0603392KFKEA" 0603 540,2670 r180 top
R32 "CRCW060359K0FKEA" 0603 1080,2420 r90 top
R33 "CRCW060380K6FKEA" 0603 1010,2420 r90 top
R34 "CRCW06031K27FKEA" 0603 710,2490 r0 top
R35 "CRCW060324K9FKEA" 0603 860,2450 r180 top
R36 "CRCW0603499RFKEA" 0603 1040,2920 r180 top
R37 "CRCW06032K00JNEA" 0603 1150,2810 r270 top
R38 "CRCW060349R9FKEA" 0603 1610,3110 r0 top
R39 "CRCW06030000Z0EA" 0603 1850,2960 r0 top
R40 "ERJ-8RQFR56V" 1206 1820,3050 r180 top
R41 "CRCW201082R0JNEF" 2010 2120,3170 r0 top
R42 "CRCW060349R9FKEA" 0603 2330,2540 r0 top
R43 "CRCW120620R0FKEA" 1206 3305,2885 r0 top
R44 "CRCW06030000Z0EA" 0603 3609.68,2440 r0 top
R45 "RC0603JR-0710KL" 0603 3309.68,2420 r90 top
R46 "CRCW0603665RFKEA" 0603 3059.25,2250 r0 top
R47 "CRCW060313K3FKEA" 0603 3670,2240 r90 top
R48 "CRCW060341K2FKEA" 0603 3750,2240 r90 top
R49 "CRCW060319K1FKEA" 0603 3368.93,2300 r180 top
R50 "CRCW04021K00JNED" 0402 3431.81,810 r180 top
R51 "CRCW04021K00JNED" 0402 3431.81,860 r180 top
R52 "ERJ-6ENF4992V" 0805_HV 2280,3310 r180 top
S1 "SKRKAEE010" SW_SKRKAEE010 4804,1573 r270 top
S2 "SKRKAEE010" SW_SKRKAEE010 3600,1850 r180 top
S3 "SKRKAEE010" SW_SKRKAEE010 3330,1850 r180 top
T1 "POE13P-50L" XFMR_POE13P 2700,2810 r0 top
TP1 "TMS-101-02-T-S" SAMTEC_TMS-101-02-T-S 3390,1170 r0 top
TP2 "TMS-101-02-T-S" SAMTEC_TMS-101-02-T-S 420,2970 r0 top
TP3 "TMS-101-02-T-S" SAMTEC_TMS-101-02-T-S 708.07,2788.07 r0 top
TP4 "TMS-101-02-T-S" SAMTEC_TMS-101-02-T-S 4059.68,2970 r0 top
TP5 "TMS-101-02-T-S" SAMTEC_TMS-101-02-T-S 4060,2270 r0 top
TP6 "TMS-101-02-T-S" SAMTEC_TMS-101-02-T-S 910,3235 r90 top
TP7 "TMS-101-02-T-S" SAMTEC_TMS-101-02-T-S 1400,2280 r270 top
TP8 "TMS-101-02-T-S" SAMTEC_TMS-101-02-T-S 1890,3340 r270 top
TP9 "TMS-101-02-T-S" SAMTEC_TMS-101-02-T-S 1050,3232 r90 top
TP10 "TMS-101-02-T-S" SAMTEC_TMS-101-02-T-S 1470,3110 r90 top
TP11 "TMS-101-02-T-S" SAMTEC_TMS-101-02-T-S 1760,2310 r90 top
U1 "TM4C129ENCPDTI3R" PDT0128A_N 2820,1130 r270 top
U2 "TPD2E2U06DRLR" DRL0005A 4660,740 r180 top
U3 "TPS23753APW" PW0014A_N 960,2700 r270 top
U4 "FOD817AS" N04C 2700,2360 r180 top
U5 "TLV431ACDBZR" DBZ0003A_N 3528.93,2250 r270 top
U6 "TPS73733DCQR" DCQ0006A_N 4540,2910 r90 top
Y1 "NX5032GA-25.000M-STD-CSK-4" NDK_NX5032GA 2975,360 r180 top

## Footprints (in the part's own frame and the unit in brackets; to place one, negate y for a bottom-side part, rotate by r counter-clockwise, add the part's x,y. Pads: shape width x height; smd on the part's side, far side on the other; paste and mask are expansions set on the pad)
0402 [mm] "0402 from SM-752 data"
  rect 0.8x0.6 smd: 1(-0.6,0) 2(0.6,0)
  silkscreen extent -1.22,-0.52 1.22,0.52, body extent -0.55,-0.3 0.55,0.3, height 0.6
0603 [mm] "0603 from SM-752 data"
  rect 1x0.95 smd: 1(-0.8,0) 2(0.8,0)
  silkscreen extent -1.52,-0.69 1.52,0.69, body extent -0.87,-0.47 0.87,0.47, height 1
0805_HV [mil] "0805 with 30mil clearance between pads"
  rect 50x63 smd: 1(-40,0) 2(40,0)
  silkscreen extent -74,-40 74,40, body extent -43,-29 43,29, height 57
1206 [mm] "1206 from SM-752 data"
  rect 1.3x1.85 smd: 1(-1.45,0) 2(1.45,0)
  silkscreen extent -2.4,-1.21 2.4,1.21, body extent -1.7,-0.9 1.7,0.9, height 1.35
1210 [mm] "1210 from SM-752 data"
  rect 1.3x2.7 smd: 1(-1.45,0) 2(1.45,0)
  silkscreen extent -2.32,-1.57 2.32,1.57, body extent -1.7,-1.35 1.7,1.35, height 1.35
1812 [mm]
  rect 1.6x3.4 smd: 1(-2,0) 2(2,0)
  silkscreen extent -0.8,-1.6 0.8,1.6, body extent -2.4,-1.7 2.4,1.7, height 1.35
2010 [mm] "Chip Capacitor, Body 5.08x2.54mm, IPC Medium Density"
  rect 1.6x2.7 smd: 1(-2.3,0) 2(2.3,0)
  silkscreen extent -3.42,-1.65 3.42,1.65, body extent -2.73,-1.45 2.73,1.45, height 1.66
Abracon_ARJP11A [mm] "RJ-45 with integrated magnetics, 14-Leads, TH"
  rect 1.4x1.4 hole 0.9: 1(-5.715,8.89)
  round 1.4 hole 0.9: 2(-4.445,6.35) 3(-3.175,8.89) 4(-1.905,6.35) 5(-0.635,8.89) 6(0.635,6.35) 7(1.905,8.89) 9(4.445,8.89) 10(5.715,6.35)
  round 1.5 hole 1: 11(-6.63,-4.06) 12(-4.09,-4.06) 13(4.09,-4.06) 14(6.63,-4.06)
  round 0 hole 3.2: MH1(-5.715,0) MH2(5.715,0)
  round 2.2 hole 1.7: S1(-7.75,3.05) S2(7.75,3.05)
  silkscreen extent -8.7,-10.9 8.13,10.69, body extent -10.33,-10.9 10.33,10.69, height 16.04
CAPSMT_62_D55 [mm] "4 x 5.2mm: Chemi-Con D55"
  rect 2.6x1.6 smd: 1(-1.8,0) 2(1.8,0)
  silkscreen extent -2.25,-2.25 2.25,2.25, body extent -2.26,-2.26 2.26,2.26, height 5.5
CAPSMT_62_HA0 [mm] "8 x 10mm:  Chemi-Con HA0"
  rect 4.2x2.2 smd: 1(-3.65,0) 2(3.65,0)
  silkscreen extent -4.25,-4.25 4.25,4.25, body extent -4.26,-4.26 4.26,4.26, height 10.5
DBZ0003A_N [mm] "SOT23, 3-Leads, Body 2.9x1.3mm, Pitch 0.95mm, Lead Span 2.4mm, IPC Medium Density"
  rrect17% 1x0.6 smd: 1(-1.2,0.95) 2(-1.2,-0.95) 3(1.2,0)
  silkscreen extent -1.65,-1.5 0.7,1.5, body extent -1.26,-1.46 1.26,1.46, height 0.98
DCQ0006A_N [mm] "SOT223, 6-Leads, Body 6.6x7.3mm (max), Pitch 1.27mm, IPC Medium Density"
  rrect17% 2.1x0.6 smd: 1(-2.975,2.54) 2(-2.975,1.27) 3(-2.975,0) 4(-2.975,-1.27) 5(-2.975,-2.54)
  rrect5% 2.1x3.2 smd: 6(2.975,0)
  silkscreen extent -1.5,-3.28 1.5,3.27, body extent -3.54,-3.25 3.54,3.25, height 1.8
DO1608C [mm] "DO1608C"
  rect 1.4x3.56 smd: 1(-2.73,0) 2(2.73,0)
  silkscreen extent -3.3,-2.55 3.3,2.55, body extent -3.27,-2.22 3.33,2.23, height 2.92
DRL0005A [mm] "SOTFL, 5-Flat Leads, Body 1.2x1.6x0.6mm, Pitch 0.5mm, TI recommended"
  rect 0.5x0.3 smd: 1(-0.75,0.5) 2(-0.75,0) 3(-0.75,-0.5) 4(0.75,-0.5) 5(0.75,0.5)
  silkscreen extent -0.9,-0.95 0.9,0.95, body extent -0.85,-0.85 0.85,0.85, height 0.62
Fiducial10-20 [mm]
  round 1 smd mask+0.5: 1(0,0)
  Component Side keep-out circle w1.178: c0,0 r0.5
Molex_39357-0002 [mm] "Terminal Block, 3.5 mm, 2x1, TH"
  rect 1.6x1.6 hole 1.1: 1(-1.75,0)
  round 1.6 hole 1.1: 2(1.75,0)
  silkscreen extent -3.86,-3.45 3.5,3.84, body extent -3.55,-3.45 3.56,3.84, height 8.51
N04C [mm] "FAIRCHILD"
  rect 1.3x1.5 smd mask+0.065: 1(-4.587,1.27) 2(-4.612,-1.27) 3(4.587,-1.27) 4(4.612,1.27)
  silkscreen extent -3.56,-2.3 3.56,2.72, body extent -5.08,-2.3 5.08,2.3, height 3.87
NDK_NX5032GA [mm] "SMD, 2-Leads Body 5x3.2mm"
  rect 2x2.4 smd: 1(-2,0) 2(2,0)
  silkscreen extent -2.6,-1.7 2.6,1.7, body extent -2.6,-1.7 2.6,1.7, height 1.5
Pb-Free_Overlay_Small [mil]
  silkscreen extent -46,-46 46,46
PDT0128A_N [mm] "Thin QFP, 128-Leads, Body 14x14mm, Pitch 0.4mm, IPC Medium Density"
  oval 1.4x0.25 smd: 1(-7.7,6.2) 2(-7.7,5.8) 3(-7.7,5.4) 4(-7.7,5) 5(-7.7,4.6) 6(-7.7,4.2) 7(-7.7,3.8) 8(-7.7,3.4) 9(-7.7,3) 10(-7.7,2.6) 11(-7.7,2.2) 12(-7.7,1.8) 13(-7.7,1.4) 14(-7.7,1) 15(-7.7,0.6) 16(-7.7,0.2) 17(-7.7,-0.2) 18(-7.7,-0.6) 19(-7.7,-1) 20(-7.7,-1.4) 21(-7.7,-1.8) 22(-7.7,-2.2) 23(-7.7,-2.6) 24(-7.7,-3) 25(-7.7,-3.4) 26(-7.7,-3.8) 27(-7.7,-4.2) 28(-7.7,-4.6) 29(-7.7,-5) 30(-7.7,-5.4) 31(-7.7,-5.8) 32(-7.7,-6.2) 65(7.7,-6.2) 66(7.7,-5.8) 67(7.7,-5.4) 68(7.7,-5) 69(7.7,-4.6) 70(7.7,-4.2) 71(7.7,-3.8) 72(7.7,-3.4) 73(7.7,-3) 74(7.7,-2.6) 75(7.7,-2.2) 76(7.7,-1.8) 77(7.7,-1.4) 78(7.7,-1) 79(7.7,-0.6) 80(7.7,-0.2) 81(7.7,0.2) 82(7.7,0.6) 83(7.7,1) 84(7.7,1.4) 85(7.7,1.8) 86(7.7,2.2) 87(7.7,2.6) 88(7.7,3) 89(7.7,3.4) 90(7.7,3.8) 91(7.7,4.2) 92(7.7,4.6) 93(7.7,5) 94(7.7,5.4) 95(7.7,5.8) 96(7.7,6.2)
  oval 0.25x1.4 smd: 33(-6.2,-7.7) 34(-5.8,-7.7) 35(-5.4,-7.7) 36(-5,-7.7) 37(-4.6,-7.7) 38(-4.2,-7.7) 39(-3.8,-7.7) 40(-3.4,-7.7) 41(-3,-7.7) 42(-2.6,-7.7) 43(-2.2,-7.7) 44(-1.8,-7.7) 45(-1.4,-7.7) 46(-1,-7.7) 47(-0.6,-7.7) 48(-0.2,-7.7) 49(0.2,-7.7) 50(0.6,-7.7) 51(1,-7.7) 52(1.4,-7.7) 53(1.8,-7.7) 54(2.2,-7.7) 55(2.6,-7.7) 56(3,-7.7) 57(3.4,-7.7) 58(3.8,-7.7) 59(4.2,-7.7) 60(4.6,-7.7) 61(5,-7.7) 62(5.4,-7.7) 63(5.8,-7.7) 64(6.2,-7.7) 97(6.2,7.7) 98(5.8,7.7) 99(5.4,7.7) 100(5,7.7) 101(4.6,7.7) 102(4.2,7.7) 103(3.8,7.7) 104(3.4,7.7) 105(3,7.7) 106(2.6,7.7) 107(2.2,7.7) 108(1.8,7.7) 109(1.4,7.7) 110(1,7.7) 111(0.6,7.7) 112(0.2,7.7) 113(-0.2,7.7) 114(-0.6,7.7) 115(-1,7.7) 116(-1.4,7.7) 117(-1.8,7.7) 118(-2.2,7.7) 119(-2.6,7.7) 120(-3,7.7) 121(-3.4,7.7) 122(-3.8,7.7) 123(-4.2,7.7) 124(-4.6,7.7) 125(-5,7.7) 126(-5.4,7.7) 127(-5.8,7.7) 128(-6.2,7.7)
  silkscreen extent -7.7,-6.3 6.3,7, body extent -8,-8 8,8, height 1.07
PW0014A_N [mm] "TSOP, 14-Leads, Body 5x4.4mm, Pitch 0.65mm, IPC Medium Density"
  oval 1.4x0.45 smd: 1(-2.95,1.95) 2(-2.95,1.3) 3(-2.95,0.65) 4(-2.95,0) 5(-2.95,-0.65) 6(-2.95,-1.3) 7(-2.95,-1.95) 8(2.95,-1.95) 9(2.95,-1.3) 10(2.95,-0.65) 11(2.95,0) 12(2.95,0.65) 13(2.95,1.3) 14(2.95,1.95)
  silkscreen extent -3.4,-2.55 1.85,2.55, body extent -3.21,-2.5 3.21,2.5, height 1
Samtec_FTSH-105-01-x-DV [mm] "Header, 1.27mm, 5x2, SMT"
  rect 2.79x0.74 smd: 1(-2.035,2.54) 2(2.035,2.54) 3(-2.035,1.27) 4(2.035,1.27) 5(-2.035,0) 6(2.035,0) 7(-2.035,-1.27) 8(2.035,-1.27) 9(-2.035,-2.54) 10(2.035,-2.54)
  silkscreen extent -3.73,-3.48 3.73,3.48, body extent -2.92,-3.17 2.92,3.18, height 5.98
SAMTEC_TMS-101-02-T-S [mm] "SAMTEC"
  rect 1.15x1.15 hole 0.66: 1(0,0)
  silkscreen extent -0.25,-1.14 0.25,1.14, body extent -0.63,-1.14 0.63,1.14, height 5.08
SM_RADIAL_C [mm] "5 x 5.8mm:  Panasonic C"
  rect 2.8x1.6 smd: 1(-2.15,0) 2(2.15,0)
  silkscreen extent -2.75,-2.75 2.75,2.75, body extent -2.76,-2.76 2.76,2.76, height 6.1
SMA [mm] "Molded Diode, 2-Leads, Body 4.3x2.6mm, IPC Medium Density, based on OnSemi component dimensions and land pattern"
  rect 2x2 smd: 1(-2,0) 2(2,0)
  silkscreen extent -3.66,-1.57 2.79,1.57, body extent -2.6,-1.3 2.6,1.3, height 2.42
SMC [mil] "Molded Diode, 2-Leads, Body 6.9x5.8mm, IPC Medium Density, based on OnSemi component dimensions and land patterns"
  rect 110x150 smd: 1(-140.49,0) 2(140.49,0)
  silkscreen extent -221,-124 189,123, body extent -156,-116 156,116, height 91
SO-8 [mm] "SOIC, 8-Leads, Body 5.0x4.0mm (max), Pitch 1.27mm, IPC Medium Density"
  rrect50% 2.2x0.6 smd: 1(-2.4,1.905) 2(-2.4,0.635) 3(-2.4,-0.635) 4(-2.4,-1.905) 5(2.4,-1.905) 6(2.4,-0.635) 7(2.4,0.635) 8(2.4,1.905)
  silkscreen extent -2.52,-2.5 0.9,2.88, body extent -3,-2.45 3,2.45, height 1.59
SOT-23 [mm] "SOT23, 3-Leads, Body 2.9x1.3mm, Pitch 0.95mm, Lead Span 2.5mm, IPC Medium Density"
  rrect50% 1x0.6 smd: 1(-1.2,0.95) 2(-1.2,-0.95) 3(1.2,0)
  silkscreen extent -1.62,-1.5 0.7,1.5, body extent -1.16,-1.45 1.21,1.45, height 1
SSOT-3 [mm] "SuperSOT-3"
  rect 1x1.4 smd: 1(-0.95,-1.1) 2(0.95,-1.1) 3(0,1.1)
  silkscreen extent -1.52,-0.05 1.5,0.78, body extent -1.52,-0.76 1.52,0.76, height 1.12
SW_SKRKAEE010 [mm] "Alps recommended land pattern"
  rect 0.8x2 smd: 1(-2.1,0) 2(2.1,0)
  silkscreen extent -1.9,-1.44 1.92,1.44, body extent -2.4,-1.45 2.4,1.45, height 1.96
TE_1981568-1 [mm] "TE Connectivity"
  rect 0.4x1.35 smd: 1(-1.3,4.225) 2(-0.65,4.225) 3(0,4.225) 4(0.65,4.225) 5(1.3,4.225)
  rect 1.6x1.4 smd: 6(-3.2,4) 7(3.2,4)
  rect 1.45x1.3 smd: 8(-3.425,1.55) 11(3.425,1.55)
  rect 1.9x1.9 smd: 9(-1.2,1.55) 10(1.2,1.55)
  silkscreen extent -3.95,-1.1 4.05,5.12, body extent -3.98,-1.12 4.02,4.48, height 2.79
TI_Stacked_Overlay_Small [mil]
  silkscreen extent -418,-98 418,98
TSW-102-07-G-S [mm] "Samtec 100mil, 1x2, 230 mil above insulator"
  rect 1.65x1.65 hole 1.016 mask+0: 1(-1.27,0)
  round 1.65 hole 1.016 mask+0: 2(1.27,0)
  silkscreen extent -2.54,-1.27 2.54,1.65, body extent -2.54,-1.27 2.54,1.27, height 8.38
TSW-103-07-G-S [mm] "Samtec 100mil, 1x3, 230 mil above insulator"
  rect 1.65x1.65 hole 1.016: 1(-2.54,0)
  round 1.65 hole 1.016: 2(0,0) 3(2.54,0)
  silkscreen extent -3.81,-1.27 3.81,1.65, body extent -3.81,-1.27 3.81,1.27, height 8.38
TSW-110-07-G-D [mm] "Samtec 100mil, 2x10, 230 mil above insulator"
  rrect6% 1.65x1.65 hole 1.016: 1(-11.43,-1.27)
  round 1.65 hole 1.016: 2(-11.43,1.27) 3(-8.89,-1.27) 4(-8.89,1.27) 5(-6.35,-1.27) 6(-6.35,1.27) 7(-3.81,-1.27) 8(-3.81,1.27) 9(-1.27,-1.27) 10(-1.27,1.27) 11(1.27,-1.27) 12(1.27,1.27) 13(3.81,-1.27) 14(3.81,1.27) 15(6.35,-1.27) 16(6.35,1.27) 17(8.89,-1.27) 18(8.89,1.27) 19(11.43,-1.27) 20(11.43,1.27)
  silkscreen extent -13.73,-2.54 12.7,2.54, body extent -12.7,-2.54 12.7,2.54, height 8.38
WL-SMCW_GREEN [mm] "WURTH"
  rect 0.8x0.8 smd: 1(-0.8,0) 2(0.8,0)
  silkscreen extent -1.9,-0.8 1.2,0.8, body extent -0.85,-0.45 0.85,0.45, height 0.8
WL-SMCW_RED_0805 [mm] "SMD, 2-Leads, Body 1.6x0.8mm"
  rect 1.1x1.2 smd: 1(-1.05,0) 2(1.05,0)
  silkscreen extent -2.4,-1.1 1.5,1.1, body extent -1,-0.62 1,0.63, height 0.7
XFMR_POE13P [mil] "Coilcraft recommended land pattern 05/04/12"
  rect 80x50 smd: 1(-335,-196.85) 2(-335,-98.43) 3(-335,0) 4(-335,98.43) 5(-335,196.85) 6(335,196.85) 7(335,98.43) 8(335,0) 9(335,-98.43) 10(335,-196.85)
  silkscreen extent -260,-266 252,264, body extent -260,-266 252,264, height 501

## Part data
C1 C3 C4 C5 C6 C7 C8 C9 C10 C11 C12 C13 C14 C19 C26 C27 C28 C29: "CAP, CERM, 0.1 µF, 16 V, +/- 10%, X7R, 0402"
C2 C18: "CAP, CERM, 1 µF, 16 V, +/- 10%, X5R, 0402"
C15 C16: "CAP, CERM, 0.01 µF, 16 V, +/- 10%, X7R, 0402"
C17: "CAP, CERM, 2.2 µF, 16 V, +/- 10%, X5R, 0402"
C20 C21: "CAP, CERM, 22 pF, 50 V, +/- 5%, C0G/NP0, 0402"
C22 C23 C24: "CAP, CERM, 0.1 µF, 25 V, +/- 5%, X7R, 0603"
C25: "CAP, CERM, 3300 pF, 50 V, +/- 10%, X7R, 0603"
C30 C43: "CAP, CERM, 2200 pF, 2000 V, +/- 10%, X7R, 1812"
C31: "CAP, CERM, 4700 pF, 2000 V, +/- 10%, X7R, 1812"
C32: "CAP, CERM, 1000 pF, 100 V, +/- 10%, X7R, 0805"
C33: "CAP, CERM, 0.1 µF, 100 V, +/- 10%, X7R, 0805"
C34: "CAP, CERM, 0.1 µF, 50 V, +/- 10%, X7R, 0603"
C35: "CAP, CERM, 0.022 µF, 50 V, +/- 10%, X7R, 0603"
C36: "CAP, CERM, 330 pF, 630 V, +/- 5%, C0G/NP0, 1206"
C37: "CAP, AL, 10 µF, 16 V, +/- 20%, SMD"
C38: "CAP, CERM, 0.22 µF, 25 V, +/- 10%, X7R, 0805"
C39: "CAP, CERM, 680 pF, 50 V, +/- 10%, X7R, 0603"
C40 C41: "CAP, CERM, 1 µF, 100 V, +/- 10%, X7R, 1210"
C42: "CAP, AL, 22 µF, 63 V, +/- 20%, 0.7 ohm, SMD"
C44: "CAP, AL, 47 µF, 6.3 V, +/- 20%, 0.7 ohm, SMD"
C45 C46: "CAP, CERM, 47 µF, 10 V, +/- 10%, X5R, 1210"
C47: "CAP, CERM, 1 µF, 16 V, +/- 10%, X7R, 0805"
C48: "CAP, CERM, 100 pF, 50 V, +/- 5%, C0G/NP0, 0603"
C49: "CAP, CERM, 8200 pF, 50 V, +/- 10%, X7R, 0603"
C50 C51: "CAP, CERM, 0.1 µF, 16 V, +/- 10%, X7R, 0603"
C52: "CAP, CERM, 2.2 µF, 16 V, +/- 10%, X5R, 0603"
C53: "CAP, CERM, 0.01 µF, 100 V, +/- 10%, X7R, 0805"
D1 D2: "LED, Red, SMD"
D3: "LED, Green, SMD"
D4: "Diode, TVS, Uni, 2.8 V, 400 W, SO-8"
D5: "Diode, TVS, Uni, 58 V, 400 W, SMA"
D6 D10: "Diode, Ultrafast, 200 V, 1 A, SMA"
D7: "Diode, Ultrafast, 75 V, 0.3 A, SOT-23"
D8: "Diode, Schottky, 40 V, 5 A, SMC"
D9: "Diode, Switching, 100 V, 0.215 A, SOT-23"
FB1 FB2: "Ferrite Bead, 30 ohm @ 100 MHz, 1.5 A, 0805"
FID1 FID2 FID3: "Fiducial mark.  There is nothing to buy or mount."
J1A J1B J2A J2B: "Header, 100mil, 10x2, Gold, TH"
J3: "Connector, Receptacle, Micro-USB Type B, R/A, Bottom Mount SMT"
J4: "Header, 1.27mm, 5x2, Gold, Black, SMT"
J5: "Header, 100mil, 3x1, Gold, TH"
J6: "Connector, RJ-45 with integrated magnetics, Gold, R/A, TH"
J7: "Terminal Block, 3.5 mm, 2x1, Tin, TH"
J8 J9 J10 J11: "Header, 100mil, 2x1, Gold, TH"
L1: "Inductor, Drum Core, Ferrite, 4.7 µH, 1.5 A, 0.09 ohm, SMD"
Logo1: library part TI_Logo, "Texas Instrument Corporate Signature"
Logo2: library part Pb-Free
Q1: "MOSFET, N-CH, 150 V, 1.6 A, SSOT-3"
R1: "RES, 51, 5%, 0.1 W, 0603"
R2: "RES, 0, 5%, 0.063 W, 0402"
R3: "RES, 4.87 k, 1%, 0.1 W, 0603"
R4 R8 R10: "RES, 100, 5%, 0.063 W, 0402"
R5 R9 R11: "RES, 10 k, 5%, 0.063 W, 0402"
R6 R7 R25 R27 R28: "RES, 330, 5%, 0.1 W, 0603"
R12: "RES, 100, 5%, 0.1 W, 0603"
R13 R14 R15 R16: "RES, 33, 5%, 0.1 W, 0603"
R17 R18 R19 R45: "RES, 10 k, 5%, 0.1 W, 0603"
R20: "RES, 1.0 M, 5%, 0.1 W, 0603"
R21 R22 R23 R24: "RES, 49.9, 1%, 0.063 W, 0402"
R26: "RES, 100 k, 1%, 0.1 W, 0402"
R29: "RES, 1.0 M, 5%, 0.25 W, 1206"
R30: "RES, 39.2 k, 1%, 0.1 W, 0603"
R31: "RES, 392 k, 1%, 0.1 W, 0603"
R32: "RES, 59.0 k, 1%, 0.1 W, 0603"
R33: "RES, 80.6 k, 1%, 0.1 W, 0603"
R34: "RES, 1.27 k, 1%, 0.1 W, 0603"
R35: "RES, 24.9 k, 1%, 0.1 W, 0603"
R36: "RES, 499, 1%, 0.1 W, 0603"
R37: "RES, 2.0 k, 5%, 0.1 W, 0603"
R38 R42: "RES, 49.9, 1%, 0.1 W, 0603"
R39 R44: "RES, 0, 5%, 0.1 W, 0603"
R40: "RES, 0.56, 1%, 0.25 W, 1206"
R41: "RES, 82, 5%, 0.75 W, 2010"
R43: "RES, 20.0, 1%, 0.25 W, 1206"
R46: "RES, 665, 1%, 0.1 W, 0603"
R47: "RES, 13.3 k, 1%, 0.1 W, 0603"
R48: "RES, 41.2 k, 1%, 0.1 W, 0603"
R49: "RES, 19.1 k, 1%, 0.1 W, 0603"
R50 R51: "RES, 1.0 k, 5%, 0.063 W, 0402"
R52: "RES, 49.9 k, 1%, 0.125 W, 0805"
S1 S2 S3: "Switch, Push Button, SMD"
T1: "Flyback Transfomer, 13W, SMD"
TP1 TP2 TP3 TP4 TP5 TP6 TP7 TP8 TP9 TP10 TP11: "Header, 1x1, Tin, TH"
U1: "Tiva C Series Microcontroller, PDT0128A"
U2: "DUAL CHANNEL HIGH SPEED ESD PROTECTION DEVICE, DRL0005A"
U3: "IEEE 802.3-2005 PoE Interface and Isolated Converter Controller with Enhanced ESD Ride-Through, -40 to 125 degC, 14-pin SOP (PW14), Green (RoHS & no Sb/Br)"
U4: "Optocoupler, 5 kV, 80-160% CTR, SMT"
U5: "Low Voltage Adjustable Precision Shunt Regulator, 39 ppm / degC, 15 mA, 0 to 70 degC, 3-pin SOT-23 (DBZ), Green (RoHS & no Sb/Br)"
U6: "Single Output LDO, 1 A, Fixed 3.3 V Output, 2.2 to 5.5 V Input, with Reverse Current Protection, 6-pin SOT-223 (DCQ), -40 to 125 degC, Green (RoHS & no Sb/Br)"
Y1: "Crystal, 25MHz,  SMD"

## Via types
v1: diameter 22, hole 10, Component Side to Solder Side, 297 vias

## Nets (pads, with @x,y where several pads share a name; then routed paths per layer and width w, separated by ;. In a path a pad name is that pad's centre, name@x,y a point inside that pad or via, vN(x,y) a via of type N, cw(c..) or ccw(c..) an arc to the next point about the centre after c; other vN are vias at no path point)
APD: R30.2 R31.1 U3.12 | length 825.4
  Component Side w6: R31.1@571.5,2670 R30.2@571.5,2600 571.5,2418.5 590,2400 765.44,2400 766.44,2399 914.56,2399 915.56,2400 930,2400 971,2441 971,2530 985.59,2544.59 U3.12@985.59,2583.86
E_SHIELD: C31.1 J6.S1 J6.S2 R29.2 | length 307.3
  Component Side w6: v1(680,470) 692.91,457.09 R29.2@760,457.09 v1(760,520) ; v1(830,470) 848.74,488.74 C31.1@920,488.74 v1(920,550)
ENETLED0: J6.11 U1.42 | length 2408.6
  Component Side w6: v1(390,1360) 1825.56,1360 1965.56,1220 2417.64,1220 2430,1232.36 U1.42@2516.85,1232.36
  Solder Side w6: J6.11@270.16,1191.02 270.16,1240.16 v1(390,1360)
ENETLED1: J6.13 U1.46 | length 2835.7
  Component Side w6: v1(390,1330) 1840,1330 1948.64,1221.36 ; 1930,1240 1961,1209 2371,1209 2410,1170 U1.46@2520,1170
  Solder Side w6: J6.13@270.16,768.98 270.16,806.49 281.16,817.49 281.16,1048.95 307.69,1075.48 307.69,1251.23 386.88,1330.43 389.57,1330.43 v1(390,1330)
EPHYRX_N: D4.1 D4.8 J6.6 R21.1 U1.53 | length 2092.1
  Component Side w6: 2440,1060 2440.87,1059.13 U1.53@2516.85,1059.13
  Component Side w10: J6.6@680,905 725,950 725,1023.79 715,1033.79 715,1086.21 738.79,1110 887.5,1110 930,1067.5 949.7,1067.5 967.2,1085 D4.1@1015.51,1085 1063.82,1085 1081.32,1067.5 1138.68,1067.5 1156.18,1085 D4.8@1204.49,1085 1252.8,1085 1269.17,1068.62 1630,1068.62 1640.75,1079.37 1707.01,1079.37 R21.1@1710,1076.38 1726.81,1076.38 1764.19,1039 2393.59,1039 2413.79,1059.19 2439.19,1059.19 2440,1060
